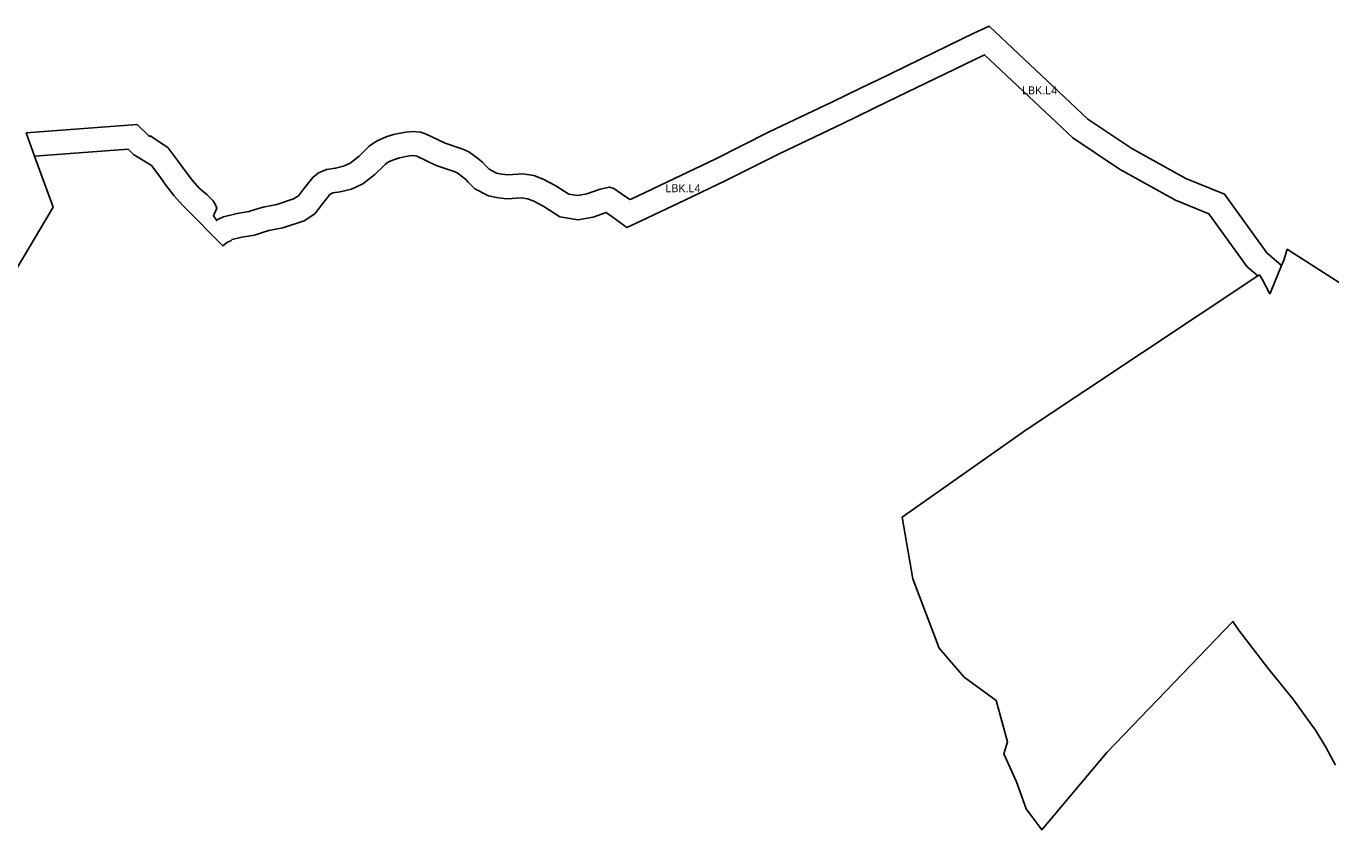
# Model space of a CAD drawing. Extents: x -450188 to -432919, y -1130252 to -1121189.
# Drawn here: x -437477 to -435847, y -1122194 to -1121189 of the extents above; entities that cross this region are included whole.
import ezdxf

# ---------------------------------------------------------------- set-up
doc = ezdxf.new("R2010")
doc.units = 0
for name, color, linetype in [('Vrstva 30', 7, 'Continuous'), ('Vrstva 32', 7, 'Continuous'), ('Vrstva 33', 7, 'Continuous'), ('Vrstva 36', 7, 'Continuous')]:
    doc.layers.add(name, color=color, linetype=linetype)

msp = doc.modelspace()

# ---------------------------------------------------------------- linework, layer by layer
at = {"layer": 'Vrstva 30'}
for p, q in [((-435937.7, -1121501.7), (-435935.6, -1121500.3)), ((-435935.6, -1121500.3), (-435932.6, -1121505.9))]:
    msp.add_line(p, q, dxfattribs=at)
for points in [[(-435921.2, -1121520.2), (-435908.2, -1121488.6), (-435905.5, -1121482), (-435901.1, -1121468.3), (-435892.7, -1121473.7), (-435824.6, -1121517.5)], [(-435840.6, -1122113.1), (-435852.8, -1122090.7), (-435865.1, -1122070.6), (-435894.3, -1122030.5), (-435924.9, -1121992.4), (-435962.1, -1121943.9), (-435969.1, -1121933.5), (-436126.4, -1122097.5), (-436208, -1122194.1), (-436227.5, -1122167.9), (-436239.5, -1122134.2), (-436255.2, -1122099), (-436250.7, -1122084.1), (-436264.9, -1122032.4), (-436304.9, -1122003.2), (-436336.2, -1121966.8), (-436369, -1121880.4), (-436382.5, -1121803.2), (-436226.1, -1121693.3), (-435937.7, -1121501.7)], [(-435932.6, -1121505.9), (-435922.8, -1121524), (-435921.2, -1121520.2)]]:
    msp.add_lwpolyline(points, dxfattribs=at)
at = {"layer": 'Vrstva 32'}
msp.add_lwpolyline([(-437477.4, -1121322.8), (-437466.8, -1121352.1), (-437443.5, -1121416), (-437541.7, -1121580.8), (-437575.9, -1121602.1), (-437641.5, -1121631), (-437684, -1121649.8), (-437689.3, -1121652.1), (-437699.4, -1121648.2), (-437703.4, -1121622.9), (-437724.2, -1121592), (-437730.9, -1121562.3), (-437732.1, -1121554.2), (-437737.6, -1121516.2), (-437741.5, -1121504.5), (-437764.5, -1121435)], dxfattribs=at)
at = {"layer": 'Vrstva 33'}
for p, q in [((-437466.8, -1121352.1), (-437477.4, -1121322.8)), ((-435932.6, -1121505.9), (-435935.6, -1121500.3))]:
    msp.add_line(p, q, dxfattribs=at)
for points in [[(-437477.4, -1121322.8), (-437477.2, -1121322.8), (-437338.5, -1121312.5), (-437324.6, -1121326.1), (-437322.7, -1121327.3), (-437322.2, -1121326.5), (-437300.4, -1121341.1), (-437287.6, -1121357.8), (-437278.5, -1121370.5), (-437269.4, -1121382.3), (-437261, -1121392), (-437251.2, -1121400.2), (-437243.7, -1121407.7), (-437240.5, -1121412.8), (-437239, -1121417.1), (-437243.2, -1121426.8), (-437239.1, -1121432.6), (-437237.9, -1121431.2), (-437230.6, -1121427.7), (-437213.5, -1121423.7), (-437199, -1121421.4), (-437189.8, -1121418.4), (-437181.2, -1121415.6), (-437163.9, -1121412.4), (-437143, -1121405.5), (-437137.1, -1121401.8), (-437130.8, -1121393.2), (-437119.2, -1121378.6), (-437112, -1121372.9), (-437101.9, -1121368.7), (-437090.6, -1121367.1), (-437080.8, -1121364.7), (-437072.4, -1121360.7), (-437061.1, -1121352.2), (-437048.4, -1121339.7), (-437039.6, -1121333.1), (-437027.3, -1121327.9), (-437018.2, -1121325), (-437003, -1121322.2), (-436994.2, -1121321.1), (-436984.5, -1121322.1), (-436978.2, -1121324.2), (-436953.5, -1121335.7), (-436931.4, -1121343.5), (-436924.1, -1121346.7), (-436914.9, -1121353.1), (-436906.9, -1121359.6), (-436903.3, -1121363.6), (-436898.6, -1121368.3), (-436889.5, -1121373.1), (-436882.6, -1121374.4), (-436875.3, -1121375.3), (-436856.7, -1121374.2), (-436842.9, -1121376.2), (-436831.3, -1121380.7), (-436815.3, -1121389.1), (-436799.2, -1121399.4), (-436788.2, -1121401.2), (-436776.5, -1121399), (-436759.7, -1121393.2), (-436748.4, -1121390.7), (-436743, -1121392.4), (-436733.1, -1121399.3), (-436722.9, -1121406.4), (-436721.3, -1121405.6), (-436667.1, -1121379.9), (-436616.1, -1121355.7), (-436548.5, -1121321.8), (-436470.3, -1121284.6), (-436432.8, -1121266.4), (-436413.3, -1121256.9), (-436307.3, -1121205.3), (-436293.6, -1121198.8), (-436273.7, -1121189.5), (-436150.2, -1121305.8), (-436095.2, -1121342.5), (-436027.7, -1121379.8), (-435979.5, -1121399.6), (-435926.8, -1121473), (-435908.2, -1121488.6), (-435921.2, -1121520.2), (-435922.8, -1121524), (-435932.6, -1121505.9)], [(-435935.6, -1121500.3), (-435937.7, -1121501.7), (-435951.1, -1121490.5), (-435998.9, -1121424.1), (-436040.7, -1121406.9), (-436110.8, -1121368.1), (-436169, -1121329.3), (-436279.4, -1121225.3), (-436280.5, -1121225.8), (-436400.2, -1121283.9), (-436457.3, -1121311.7), (-436535.3, -1121348.8), (-436602.9, -1121382.6), (-436654.2, -1121407), (-436708.5, -1121432.8), (-436726.6, -1121441.2), (-436745.5, -1121427.4), (-436750.6, -1121423.7), (-436752.4, -1121422.4), (-436768.8, -1121428.1), (-436787.9, -1121431.7), (-436810.2, -1121427.9), (-436830.4, -1121415), (-436843.8, -1121408), (-436850.6, -1121405.4), (-436857.9, -1121404.3), (-436876.2, -1121405.4), (-436887.2, -1121404.1), (-436899.5, -1121401.6), (-436916.6, -1121392.8), (-436925, -1121384.4), (-436927.7, -1121381.4), (-436933, -1121377), (-436938.8, -1121373), (-436942.4, -1121371.4), (-436964.9, -1121363.6), (-436989.2, -1121352.1), (-436990.8, -1121351.6), (-436993.9, -1121351.3), (-436998.4, -1121351.8), (-437010.8, -1121354.1), (-437016.9, -1121356.1), (-437024.5, -1121359.3), (-437028.8, -1121362.5), (-437041.5, -1121374.9), (-437056.7, -1121386.5), (-437070.7, -1121393.1), (-437084.8, -1121396.6), (-437093.9, -1121397.9), (-437096.7, -1121399), (-437097.9, -1121399.9), (-437107, -1121411.5), (-437116.4, -1121424.1), (-437130, -1121432.8), (-437156.4, -1121441.5), (-437173.8, -1121444.8), (-437180.6, -1121446.9), (-437192, -1121450.6), (-437207.7, -1121453.1), (-437219.9, -1121456), (-437221.5, -1121457.7), (-437225.8, -1121459.6), (-437231.3, -1121464.1), (-437279.7, -1121415.5), (-437282.1, -1121413.4), (-437292.6, -1121401.3), (-437302.6, -1121388.4), (-437311.7, -1121375.7), (-437320.7, -1121363.9), (-437343.3, -1121349.8), (-437349.8, -1121343.4), (-437466.8, -1121352.1)]]:
    msp.add_lwpolyline(points, dxfattribs=at)

# ---------------------------------------------------------------- texts
at = {"layer": 'Vrstva 36'}
for p in [(-436232.6, -1121274.8), (-436678.4, -1121397.1)]:
    msp.add_text('LBK.L4', height=10, dxfattribs=at).set_placement(p)

doc.saveas('drawing.dxf')
